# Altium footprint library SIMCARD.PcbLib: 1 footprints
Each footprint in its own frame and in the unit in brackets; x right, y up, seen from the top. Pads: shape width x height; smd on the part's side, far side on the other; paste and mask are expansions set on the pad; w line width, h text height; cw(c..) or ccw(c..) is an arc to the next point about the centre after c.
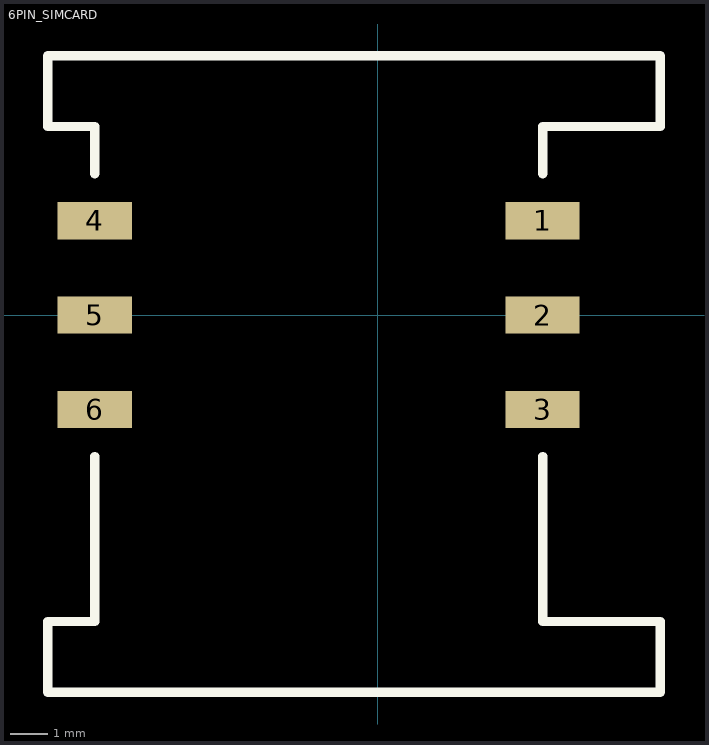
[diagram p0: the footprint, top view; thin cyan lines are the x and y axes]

## 6PIN_SIMCARD [mm]
pads (6):
  rect 2x1 smd: 1(4.445,2.54) 2(4.445,0) 3(4.445,-2.54) 4(-7.62,2.54) 5(-7.62,0) 6(-7.62,-2.54)
Top Overlay:
  lines w0.254: -7.62,-3.81 -7.62,-8.255 -8.89,-8.255 -8.89,-10.16 7.62,-10.16 7.62,-8.255 4.445,-8.255 4.445,-3.81 ; -7.62,3.81 -7.62,5.08 -8.89,5.08 -8.89,6.985 7.62,6.985 7.62,5.08 4.445,5.08 4.445,3.81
